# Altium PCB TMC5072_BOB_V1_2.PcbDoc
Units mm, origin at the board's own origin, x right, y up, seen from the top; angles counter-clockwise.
Board outline 25.4 x 35.56 mm, 4 copper layers (Top, GND, VM, Bottom), stack 0.704 mm thick; 32 components, 35 nets, 115 pads, 104 vias.
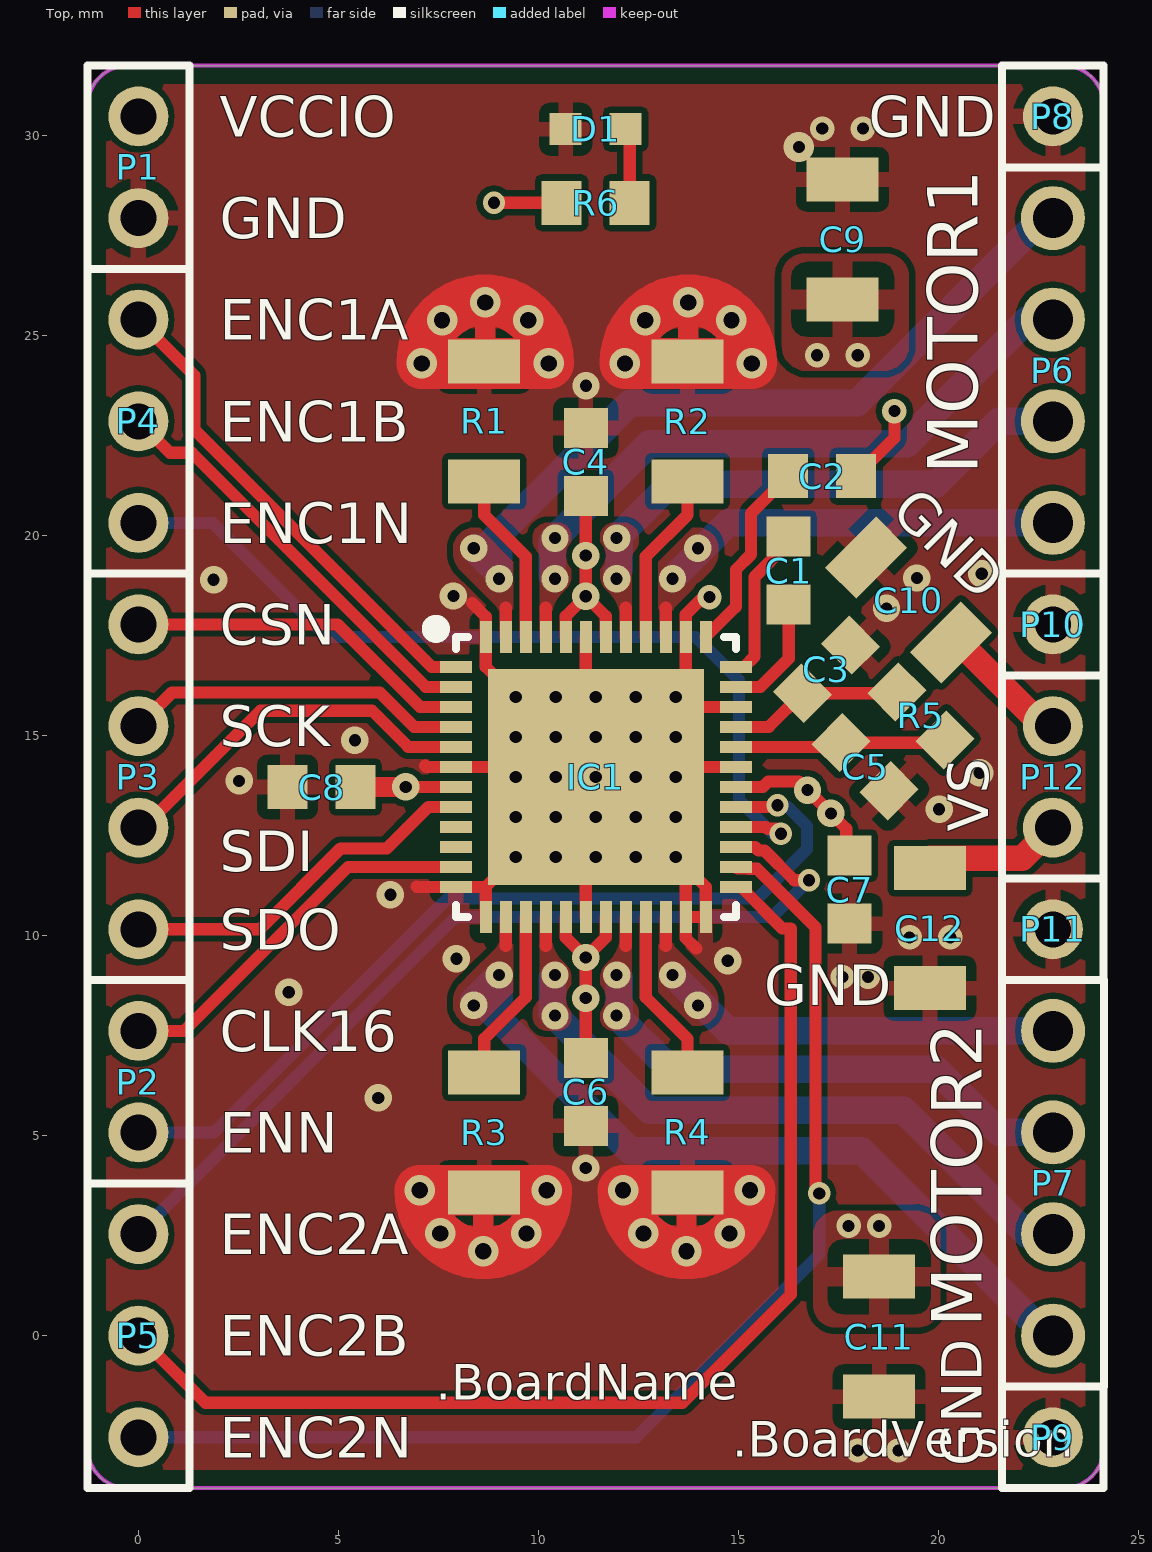
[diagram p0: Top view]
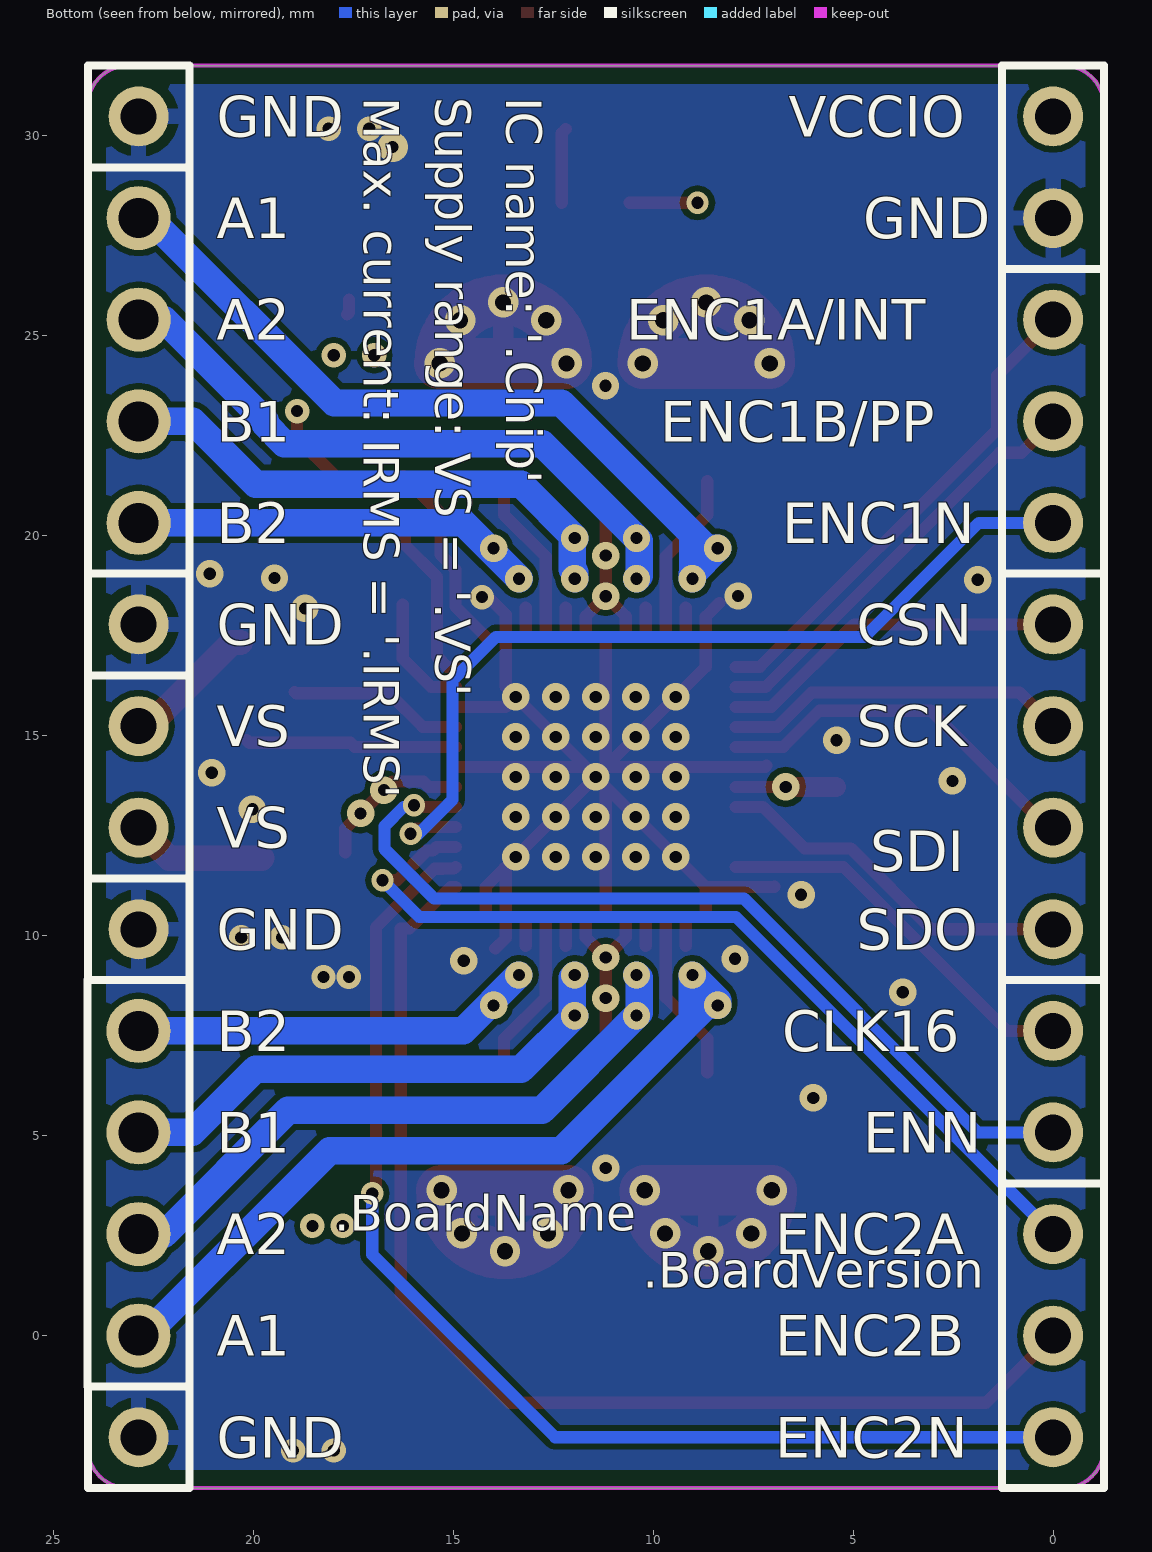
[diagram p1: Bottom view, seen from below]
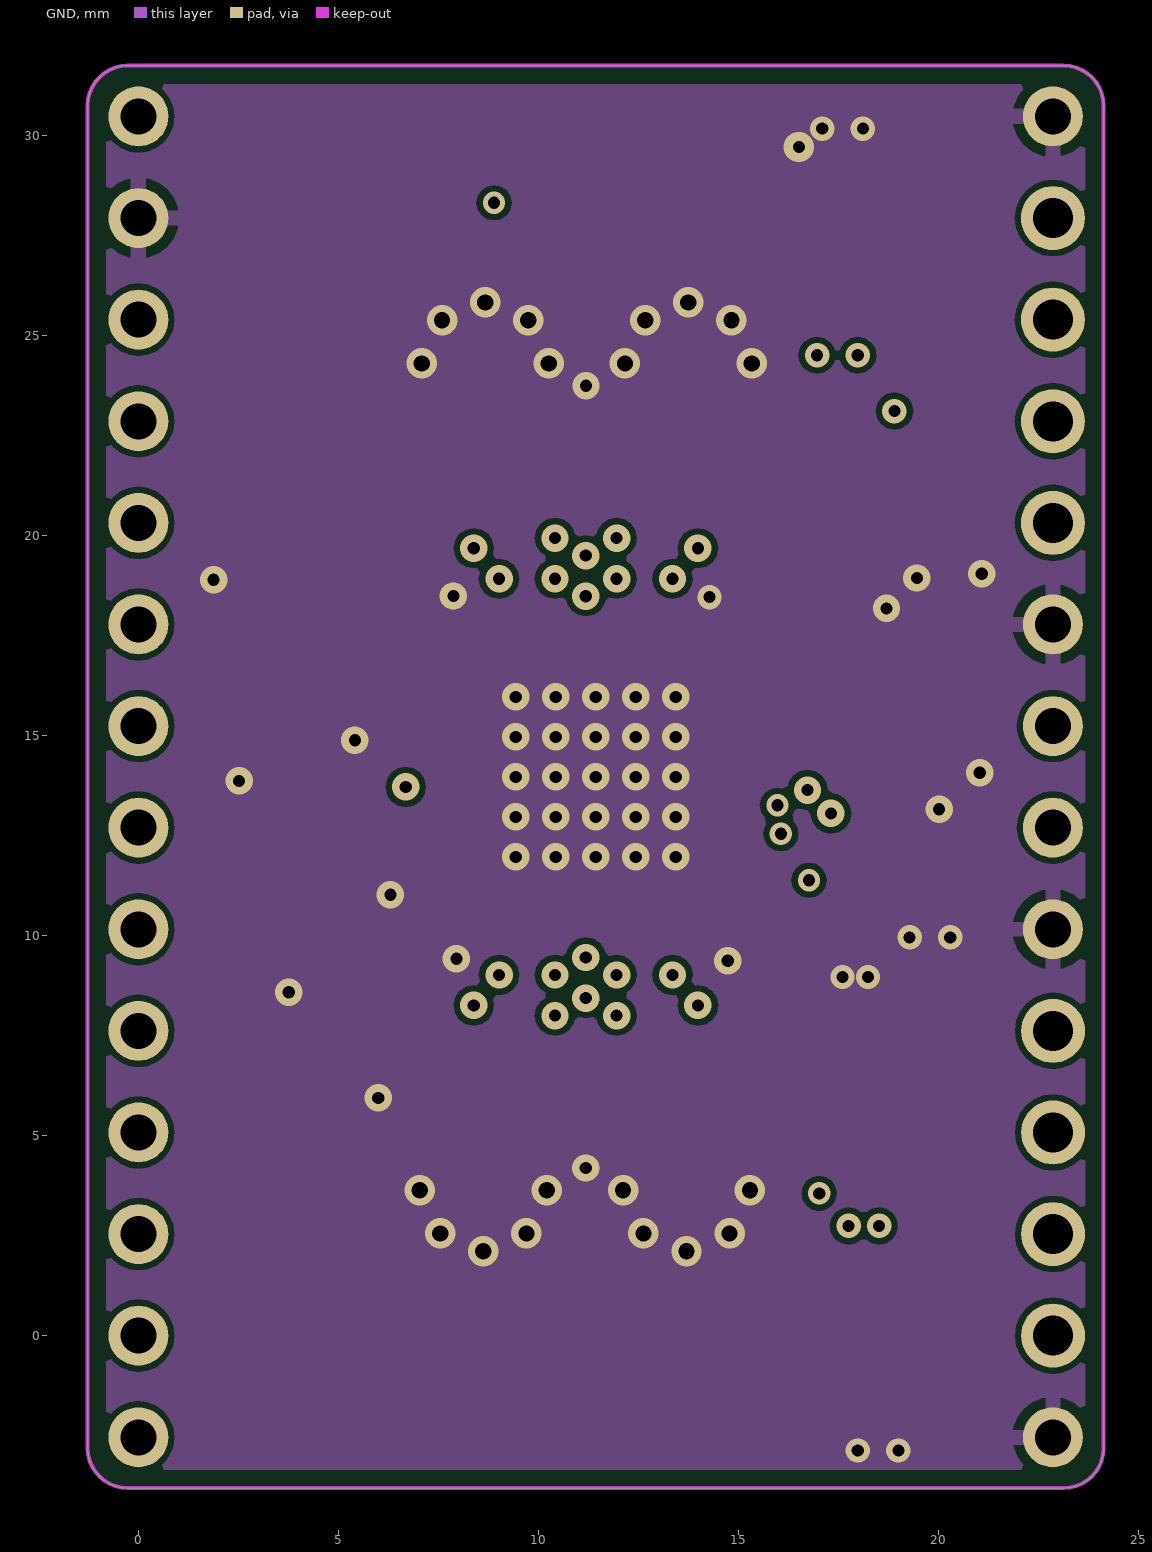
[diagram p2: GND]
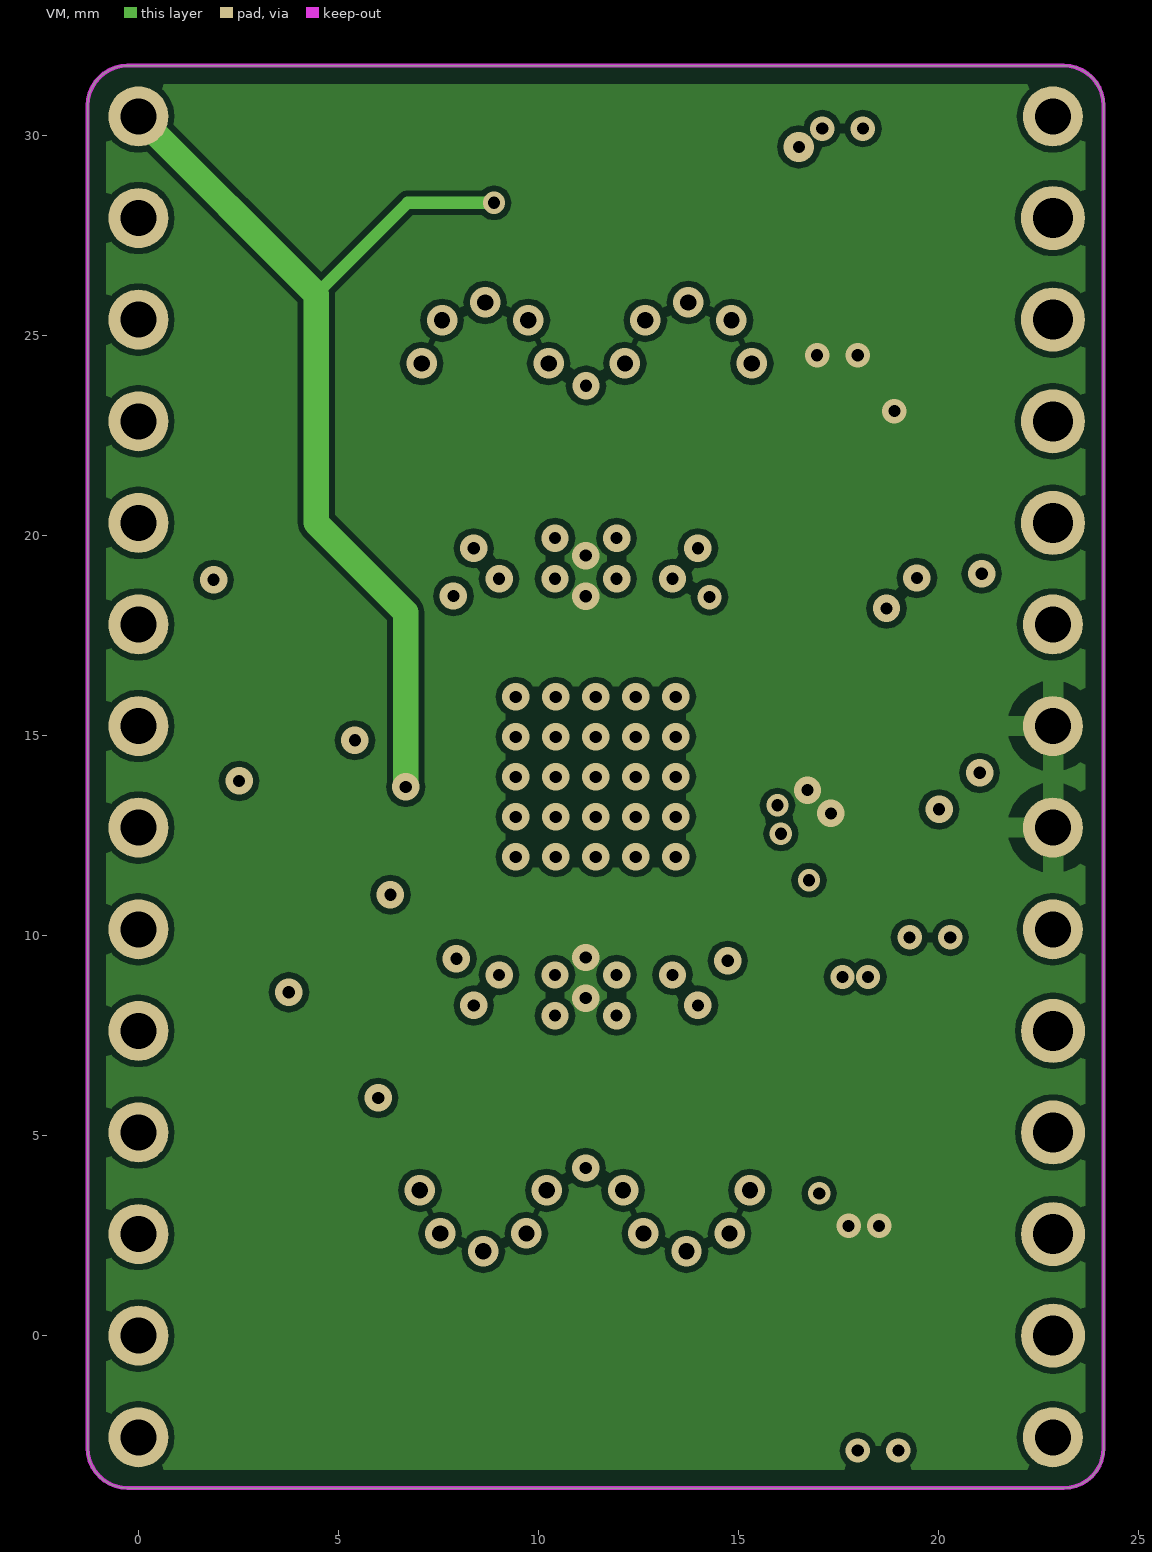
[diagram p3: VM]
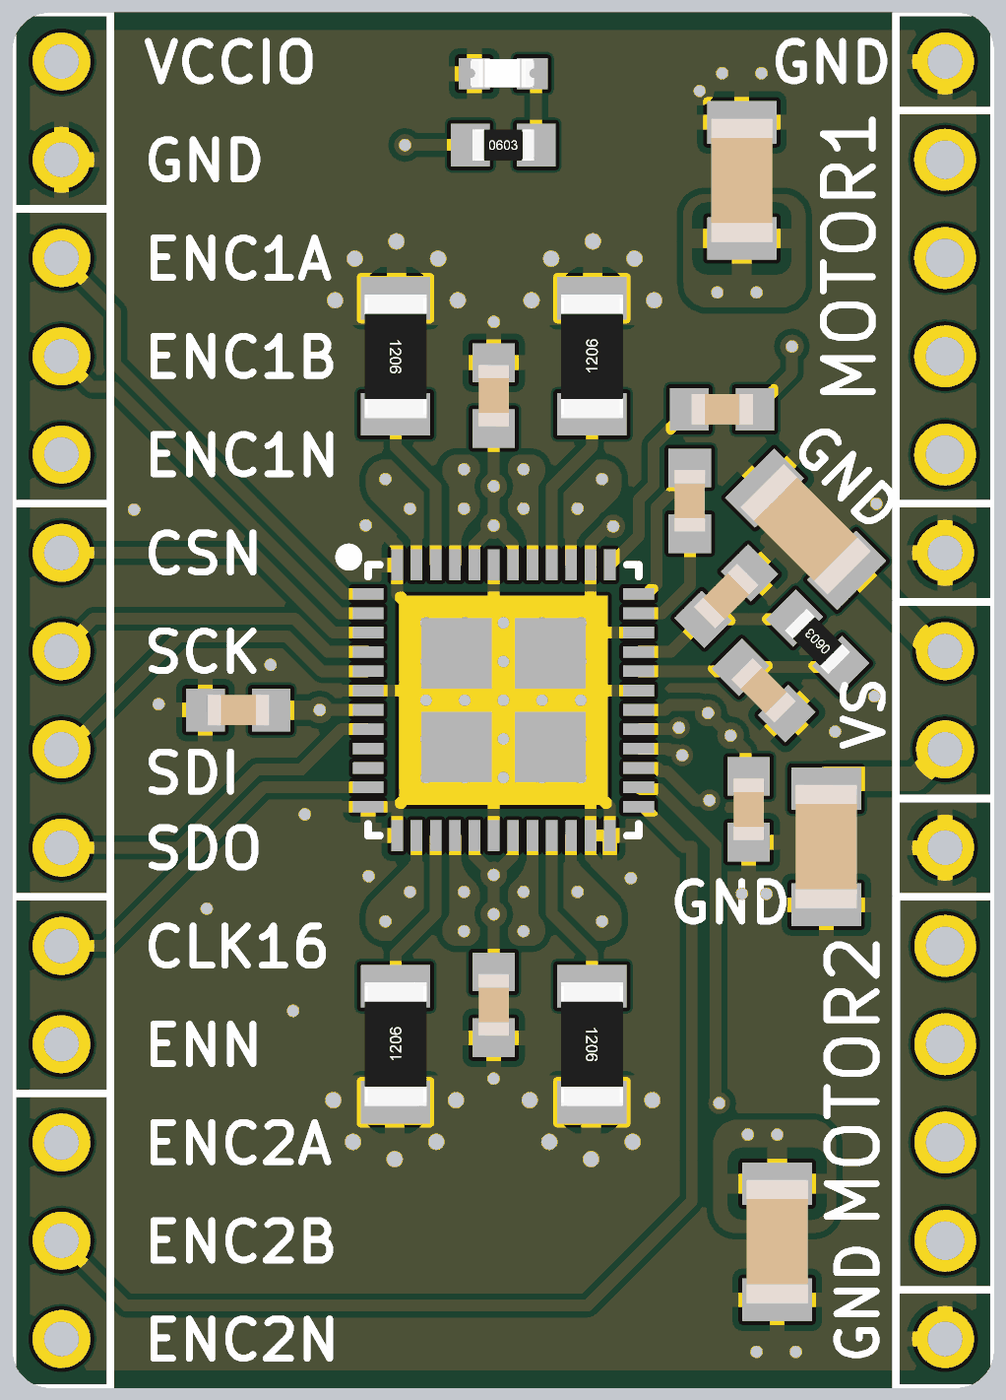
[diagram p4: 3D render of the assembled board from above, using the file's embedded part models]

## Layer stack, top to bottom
Top Solder: solder mask 0.0102, Solder Resist, Dk 3.5
Top: signal copper 0.035
Dielectric 1: core 0.2, FR-4, Dk 4.8
GND: signal copper 0.0175
Dielectric 2: prepreg 0.127, FR-4, Dk 4.2
VM: signal copper 0.0356
Dielectric4: core 0.254, FR-4, Dk 4.2
Bottom: signal copper 0.035
Bottom Solder: solder mask 0.0102, Solder Resist, Dk 3.5

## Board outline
-1.27,-2.81 ccw(c-0.27,-2.81) -0.27,-3.81 23.13,-3.81 ccw(c23.13,-2.81) 24.13,-2.81 24.13,30.75 ccw(c23.13,30.75) 23.13,31.75 -0.27,31.75 ccw(c-0.27,30.75) -1.27,30.75

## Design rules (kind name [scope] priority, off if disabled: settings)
Clearance BoardOutlineClearance [OnLayer('Keep-Out Layer')] p1: gap=0.4 ignorepadtopadclearanceinfootprint=FALSE except(0: Arc-Hole Track-Hole SMDPad-Hole THPad-Hole Via-Hole Fill-Hole Poly-Hole Region-Hole Text-Hole)
Clearance "Fiducial Clearance" [HasFootprint('FIDUCIAL_40MIL')] p2: gap=0.66 ignorepadtopadclearanceinfootprint=FALSE except(0: Arc-Hole Track-Hole SMDPad-Hole THPad-Hole Via-Hole Fill-Hole Poly-Hole Region-Hole Text-Hole)
Clearance "Mounting Hole Clearance" [(HoleDiameter >= 110) And  IsPad  And ((PadYSize_AllLayers - HoleDiameter)  <=  1)] p3: gap=0.762 ignorepadtopadclearanceinfootprint=FALSE except(0: Arc-Hole Track-Hole SMDPad-Hole THPad-Hole Via-Hole Fill-Hole Poly-Hole Region-Hole Text-Hole)
Clearance [All] p4: gap=0.152 ignorepadtopadclearanceinfootprint=FALSE except(0: Arc-Hole Track-Hole SMDPad-Hole THPad-Hole Via-Hole Fill-Hole Poly-Hole Region-Hole Text-Hole)
ComponentClearance [All] p1: gap=0 collisioncheckmode=3 verticalgap=0.254 showdistances=FALSE
DiffPairsRouting [All] p1 off: maxlimit=0.254 minlimit=0.191 mostfreqgap=0.254 toplayer_prefgap=0.191 toplayer_minwidth=0.191 toplayer_maxwidth=0.191 toplayer_prefwidth=0.191 midlayer1_prefgap=0.191 midlayer1_minwidth=0.191 midlayer1_maxwidth=0.191 midlayer1_prefwidth=0.191 midlayer2_mingap=0.254 midlayer2_minwidth=0.381 midlayer2_maxwidth=0.381 midlayer2_prefwidth=0.381 bottomlayer_prefgap=0.191 bottomlayer_minwidth=0.191 bottomlayer_maxwidth=0.191 bottomlayer_prefwidth=0.191 maxuncoupledlength=12.7
HoleSize [All] p1: absolutevalues=TRUE maxlimit=2540 minlimit=0.3 maxpercent=80.000 minpercent=20.000
HoleToHoleClearance [All] p1: gap=0.203 allowstackedmicrovias=TRUE
MatchedLengths "SD_CARD MatchedLengths" [InNetClass('SD_CARD')] p1: tolerance=0.254 checknetsindiffpair=FALSE checkdiffpairvsdiffpair=TRUE checkxsignals=TRUE checkothers=TRUE
MinimumAnnularRing MinimumViaAnnualRing [All] p1: minimumring=0.125
MinimumSolderMaskSliver STM32_MinimumSolderMaskSliver [(InComponent('STM1') AND InComponent('STM2')) vs (InComponent('STM1') AND InComponent('STM2'))] p1: minsoldermaskwidth=0.025
MinimumSolderMaskSliver USB_HUB_MinimumSolderMaskSliver [InComponent('USB_HUB')] p2: minsoldermaskwidth=0.025
MinimumSolderMaskSliver [All] p3 off: minsoldermaskwidth=0.038
PasteMaskExpansion TestPadPasteMaskExpansion [HasFootprint('SMD_TP_2X2_ROUND')] p1: expansion=-2
PasteMaskExpansion [All] p2: expansion=0
PlaneClearance [All] p1: clearance=1.016
PlaneConnect VM_PlaneConnect [OnLayer('VM') AND InNet('VM')] p1: planeconnectstyle=Relief reliefexpansion=0.508 reliefentries=4 reliefconductorwidth=0.508 reliefairgap=0.254
PlaneConnect [All] p2: planeconnectstyle=Relief reliefexpansion=0.508 reliefentries=4 reliefconductorwidth=0.254 reliefairgap=0.254
PolygonConnect VSAViaConnectStyle [InNet('VM') AND IsVia] p1: connectstyle=Direct reliefconductorwidth=0.508 reliefentries=4 polygonreliefangle="90 Angle" airgapwidth=0.203
PolygonConnect VSAConnectStyle [InNet('VM')] p2: connectstyle=Relief reliefconductorwidth=0.508 reliefentries=4 polygonreliefangle="90 Angle" airgapwidth=0.381
PolygonConnect MotorPhaceConnectStyle [(IsVia OR IsPad) AND InNetClass('MotorPower')] p3: connectstyle=Direct reliefconductorwidth=0.254 reliefentries=4 polygonreliefangle="90 Angle" airgapwidth=0.254
PolygonConnect ThermalVias [IsVia] p4: connectstyle=Direct reliefconductorwidth=0.254 reliefentries=4 polygonreliefangle="90 Angle" airgapwidth=0.254
PolygonConnect [All] p5: connectstyle=Relief reliefconductorwidth=0.381 reliefentries=4 polygonreliefangle="90 Angle" airgapwidth=0.254
RoutingVias [All] p1: holewidth=0.305 width=0.559 viastyle="Through Hole" minholewidth=0.305 minwidth=0.559 maxholewidth=0.305 maxwidth=1.27
ShortCircuit [All] p1 off: allowed=FALSE
SilkToBoardRegionClearance [All] p1 off:
SilkToSilkClearance [All] p1 off: silktosilkclearance=0.254
SilkToSolderMaskClearance [IsPad] p1 off: minsilkscreentomaskgap=0.254 clearancetoexposedcopper=TRUE
SolderMaskExpansion FiducialSolderMaskExpansion [HasFootprint('FIDUCIAL_40MIL')] p1: expansion=0.66
SolderMaskExpansion [All] p2: expansion=0.102
UnRoutedNet [All] p1 off:
Width VIN_Width [InNetClass('PWR_VIN')] p1: maxlimit=7.62 minlimit=5.08 preferedwidth=5.334
Width Other_Width [All] p2: maxlimit=2540 minlimit=0.203 preferedwidth=0.3 minimp=50.000000 maximp=50.000000 favimp=50.000000
17 further rules are at their usual default settings.

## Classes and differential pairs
differential pair class USB_DIFF: STM_USB STM_USB_D

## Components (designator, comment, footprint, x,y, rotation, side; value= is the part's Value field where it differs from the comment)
C1 "22nF" C0603 16.256,19.126 r90 top
C2 "100nF" C0603 17.094,21.488 r180 top
C3 "470nF" C0603 17.2,16.662 r45 top
C4 "100nF" C0603 11.184,21.844 r90 top
C5 "4.7uF" C0603 18.165,14.224 r315 top
C6 "100nF" C0603 11.184,6.096 r90 top
C7 "100nF" C0603 17.78,11.151 r90 top
C8 "100nF" C0603 4.576,13.716 r180 top
C9 "10uF" C1206 17.602,27.407 r90 top
C10 "10uF" C1206 19.253,18.39 r135 top
C11 "10uF" C1206 18.517,-0.025 r270 top
C12 "10uF" C1206 19.787,10.185 r270 top
D1 "LED, Blue, SMD, 20mA, 2.8V, 465 nm" LED_0603 11.43,30.163 r180 top
IC1 "TMC5072-LA" TMC5072_QFN48_0.5_7.0X7.0 11.434,13.97 r270 top
P1 "VCC" 2_PIN_THT 0,30.48 r180 top
P2 "VCC" 2_PIN_THT 0,7.62 r180 top
P3 "SPI" 4_PIN_THT 0,10.16 r0 top
P4 "ENC1" 3_PIN_THT 0,20.32 r0 top
P5 "ENC2" 3_PIN_THT 0,-2.54 r0 top
P6 "MOTOR1" 4_PIN_THT_1mm_hole 22.86,27.94 r180 top
P7 "MOTOR2" 4_PIN_THT_1mm_hole 22.864,0 r0 top
P8 "GND" TH_PIN 22.86,30.48 r0 top
P9 "GND" TH_PIN 22.86,-2.54 r90 top
P10 "GND" TH_PIN 22.86,17.78 r0 top
P11 "GND" TH_PIN 22.86,10.16 r0 top
P12 "PWR" 2_PIN_THT 22.86,12.7 r0 top
R1 "0R27/1%/R1206" R1206 8.644,22.86 r270 top
R2 "0R27/1%/R1206" R1206 13.724,22.86 r90 top
R3 "0R27/1%/R1206" R1206 8.644,5.08 r90 top
R4 "0R27/1%/R1206" R1206 13.724,5.08 r270 top
R5 "2R2/1%/" R0603 19.562,15.494 r135 top
R6 "1k" R0603 11.43,28.321 r0 top

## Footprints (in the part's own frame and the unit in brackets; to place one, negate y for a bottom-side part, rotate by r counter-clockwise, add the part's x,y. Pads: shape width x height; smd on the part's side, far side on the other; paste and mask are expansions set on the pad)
2_PIN_THT [mm]
  round 1.5 hole 0.9: 1(0,0) 2(0,2.54)
  silkscreen extent -1.27,-1.27 1.27,3.81
3_PIN_THT [mm]
  round 1.5 hole 0.9: 1(0,0) 2(0,2.54) 3(0,5.08)
  silkscreen extent -1.27,-1.27 1.27,6.35
4_PIN_THT [mm]
  round 1.5 hole 0.9: 1(0,0) 2(0,2.54) 3(0,5.08) 4(0,7.62)
  silkscreen extent -1.27,-1.27 1.27,8.89
4_PIN_THT_1mm_hole [mm]
  round 1.6 hole 1: 1(0,0) 2(0,2.54) 3(0,5.08) 4(0,7.62)
  silkscreen extent -1.27,-1.27 1.27,8.89
C0603 [mm] "0603 ceramic capacitor"
  rect 1x1.1 smd: 1(-0.85,0) 2(0.85,0)
  body extent -0.8,-0.4 0.8,0.4, height 0.8
C1206 [mm] "1206 ceramic capacitor"
  rect 1.1x1.8 smd: 1(-1.5,0) 2(1.5,0)
  body extent -1.6,-0.8 1.6,0.8, height 0.76
LED_0603 [mm]
  rect 0.8x0.8 smd: 1(-0.75,0) 2(0.75,0)
  body extent -0.8,-0.38 0.85,0.35, height 0.68
R0603 [mm] "0603 resistor"
  rect 1x1.1 smd: 1(-0.85,0) 2(0.85,0)
  body extent -0.8,-0.4 0.8,0.4, height 0.45
R1206 [mm] "1206 resistor"
  rect 1.1x1.8 smd: 1(-1.5,0) 2(1.5,0)
  body extent -1.6,-0.8 1.6,0.8, height 0.6
TH_PIN [mm]
  round 1.5 hole 0.9: 1(0,0)
  silkscreen extent -1.27,-1.27 1.27,1.27
TMC5072_QFN48_0.5_7.0X7.0 [mm]
  rect 0.3x0.8 smd: 1(-2.75,-3.5) 2(-2.25,-3.5) 3(-1.75,-3.5) 4(-1.25,-3.5) 5(-0.75,-3.5) 6(-0.25,-3.5) 7(0.25,-3.5) 8(0.75,-3.5) 9(1.25,-3.5) 10(1.75,-3.5) 11(2.25,-3.5) 12(2.75,-3.5) 25(2.75,3.5) 26(2.25,3.5) 27(1.75,3.5) 28(1.25,3.5) 29(0.75,3.5) 30(0.25,3.5) 31(-0.25,3.5) 32(-0.75,3.5) 33(-1.25,3.5) 34(-1.75,3.5) 35(-2.25,3.5) 36(-2.75,3.5)
  rect 0.8x0.3 smd: 13(3.5,-2.75) 14(3.5,-2.25) 15(3.5,-1.75) 16(3.5,-1.25) 17(3.5,-0.75) 18(3.5,-0.25) 19(3.5,0.25) 20(3.5,0.75) 21(3.5,1.25) 22(3.5,1.75) 23(3.5,2.25) 24(3.5,2.75) 37(-3.5,2.75) 38(-3.5,2.25) 39(-3.5,1.75) 40(-3.5,1.25) 41(-3.5,0.75) 42(-3.5,0.25) 43(-3.5,-0.25) 44(-3.5,-0.75) 45(-3.5,-1.25) 46(-3.5,-1.75) 47(-3.5,-2.25) 48(-3.5,-2.75)
  rect 5.4x5.4 smd paste-25.4: 49(0,0)
  silkscreen extent -3.8,-4.1 3.5,3.5, body extent -3.5,-3.5 3.5,3.5, height 0.9

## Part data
C1: library part Capacitor, "Ceramic capacitor", MPN=MC0603B223K500CT, Voltage rating=50V
C2 C4 C6 C7: library part Capacitor, "Ceramic capacitor", MPN=MC0603F104M500CT, Voltage rating=50V
C3: library part Capacitor, "Ceramic capacitor", MPN=MC0603X474K160CT, Voltage rating=16V
C5: library part Capacitor, "Ceramic capacitor", MPN=MC0603X475K100CT, Voltage rating=10V
C8: library part Capacitor, "Ceramic capacitor", Manufacturer=Multicomp, MPN=MC0603F104M500CT, Voltage rating=50V
C9 C10 C11 C12: library part "10 µF, 25 V, ± 10%, X5R, MC Series, 1206 [3216 Metric]", "SMD Multilayer Ceramic Capacitor, 1206 [3216 Metric], 10 µF, 25 V, ± 10%, X5R, MC Series", MPN=MC1206X106K250CT, Voltage rating=25V
D1: Colour=Blue, Current rating=20mA, MPN=LTST-C191TBKT-5A
IC1: "Dual low-noise operation controllerfor up to two 2-phase bipolar stepper motors, with SPI, Step/Dir, UART, QFN48(7x7)"
P1 P2 P12: library part "Header 2", "Header, 2-Pin"
P3: library part "Header 4", "Header, 4-Pin"
P4 P5: library part "Header 3", "Header, 3-Pin"
P6 P7: library part "Wire-To-Board Connector, 2.5 mm, 4 Contacts, Header, EH Series, Through Hole, 1 Rows", "Wire-To-Board Connector, 2.5 mm, 4 Contacts, Header, EH Series, Through Hole, 1 Rows", MPN=B4B-EH-A
P8 P9 P10 P11: library part PIN
R1 R2 R3 R4: library part Resistor, "Resistor", MPN=RCWE1206R270FKEA, Power rating=0.5W, Resistance=0R27, Temp coefficient=*ppm, Voltage rating=*V
R5: library part Resistor, "Resistor", MPN=MC0063W060312R2, Power rating=*mW, Resistance=2R2, Temp coefficient=*ppm, Voltage rating=*V
R6: library part "1 kohm, 50 V, 0603 [1608 Metric], 63 mW, ± 1%, MC Series", "1 kohm, 50 V, 0603 [1608 Metric], 63 mW, ± 1%, MC Series", MPN=MC0063W060311K, PowerRating=63mW, Temp coefficient=*ppm, VoltageRating=50V

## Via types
v1: diameter 0.686, hole 0.305, Top to Bottom, tented both sides, 58 vias
v2: diameter 0.762, hole 0.406, Top to Bottom, tented both sides, 20 vias
v3: diameter 0.61, hole 0.305, Top to Bottom, tented both sides, 14 vias
v4: diameter 0.688, hole 0.305, Top to Bottom, tented both sides, 6 vias
v5: diameter 0.559, hole 0.305, Top to Bottom, tented both sides, 5 vias
v6: diameter 0.757, hole 0.3, Top to Bottom, tented both sides, 1 vias

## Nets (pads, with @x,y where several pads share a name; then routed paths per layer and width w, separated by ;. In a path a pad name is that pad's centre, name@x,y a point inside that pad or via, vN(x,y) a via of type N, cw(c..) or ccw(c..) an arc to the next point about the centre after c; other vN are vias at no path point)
5V_OUT: C5.1 IC1.32 R5.1 | length 5.3
  Top w0.305: IC1.32 17.459,14.72 C5.1 20.095,14.825 R5.1
BR1A: IC1.46 R1.2 | length 4.3
  Top w0.305: R1.2 8.644,20.518 9.684,19.478 IC1.46
BR1B: IC1.40 R2.1 | length 4.3
  Top w0.305: IC1.40 12.684,19.478 13.724,20.518 R2.1
BR2A: IC1.15 R3.2 | length 4.3
  Top w0.305: R3.2 8.644,7.422 9.684,8.462 IC1.15
BR2B: IC1.21 R4.1 | length 4.3
  Top w0.305: IC1.21 12.684,8.462 13.724,7.422 R4.1
CLK16: IC1.11 P2.1 | length 9.6
  Top w0.305: P2.1 1.143,7.62 5.243,11.72 IC1.11
CPI: C1.2 IC1.36 | length 4
  Top w0.305: IC1.36 15.145,16.72 15.401,16.976 15.401,18.97 16.206,19.774 16.206,19.976 C1.2
CPO: C1.1 IC1.35 | length 3
  Top w0.305: IC1.35 15.549,16.22 16.256,16.927 C1.1
CSN: IC1.3 P3.4 | length 8.8
  Top w0.305: P3.4 4.976,17.78 7.036,15.72 IC1.3
ENC1N: IC1.28 P4.1 | length 22.2
  Top w0.305: IC1.28 15.689,12.72 15.735,12.675 15.934,12.675 v5(16.061,12.548)
  Bottom w0.305: P4.1 1.854,20.32 4.704,17.47 13.924,17.47 15.011,16.383 15.011,13.398 15.862,12.548 v5(16.061,12.548)
ENC2A: IC1.27 P5.3 | length 22.6
  Top w0.305: IC1.27 15.415,12.22 15.503,12.132 15.65,12.132 16.397,11.385 v5(16.764,11.385)
  Bottom w0.305: P5.3 7.93,10.47 15.849,10.47 v5(16.764,11.385)
ENC2B: IC1.25 P5.2 | length 36.8
  Top w0.305: P5.2 1.676,-1.676 13.603,-1.676 16.307,1.028 16.307,10.182 ; IC1.25 15.056,11.22 16.094,10.182 16.307,10.182 ; 16.307,2.475 16.307,10.182
ENC2N: IC1.26 P5.1 | length 29.7
  Top w0.305: IC1.26 14.977,11.677 15.246,11.677 15.248,11.675 15.461,11.675 16.925,10.21 16.925,3.649 v5(17.018,3.556)
  Bottom w0.305: P5.1 12.446,-2.54 17.018,2.032 v5(17.018,3.556)
ENN: IC1.29 P2.2 | length 22.2
  Top w0.305: IC1.29 v5@16.002,13.22
  Bottom w0.305: P2.2 1.88,5.08 7.727,10.927 15.474,10.927 16.713,12.167 16.713,12.737 16.23,13.22 v5@16.002,13.22
  other v5: 15.977,13.259
GND: C3.2 C4.2 C5.2 C6.1 C7.1 C8.2 C9.2 C10.2 C11.2 C12.2 D1.2 IC1.6 IC1.12 IC1.13 IC1.18 IC1.23 IC1.24 IC1.31 IC1.34 IC1.38 IC1.43 IC1.48 IC1.49 P1.2 P8.1 P9.1 P10.1 P11.1 R1.1 R2.2 R3.1 R4.2 | length 78.6
  Top w0.305: 6.96,11.227 6.966,11.22 IC1.12 8.684,11.22 ; 7.163,14.249 7.192,14.22 IC1.6 IC1.49@11.184,14.22 ; 8.344,18.313 8.684,17.973 IC1.48 8.684,16.72 v1(9.434,15.97) v1(10.434,14.97) IC1.49@11.184,14.22 ; IC1.13 8.684,11.22 ; IC1.18 IC1.49@11.184,13.72 ; IC1.43 IC1.49@11.184,14.22 ; 13.945,9.677 13.684,9.938 IC1.23 ; v3(14.275,18.464) 14.121,18.464 13.684,18.028 IC1.38 13.684,16.22 v1(13.434,15.97) ; IC1.31 IC1.49@11.684,14.22 ; IC1.34 13.684,15.72 v1(13.434,15.97) ; 8.684,11.22 v1(9.434,11.97) v1(10.434,12.97) IC1.49@11.184,13.72 ; IC1.49@11.184,13.72 v1(11.434,13.97) ; IC1.49@11.184,14.22 v1(11.434,13.97) ; v1(11.434,13.97) v1(12.434,12.97) v1(13.434,11.97) IC1.49@13.718,11.686 ; v1(11.434,13.97) IC1.49@11.684,14.22 ; IC1.49@11.684,14.22 v1(12.434,14.97) v1(13.434,15.97) ; IC1.23 13.684,11.652 IC1.49@13.718,11.686 ; IC1.23 IC1.24 14.184,11.22 IC1.49@13.718,11.686
  Top w0.508: v2@8.621,2.248 R3.1@8.621,3.634 ; R1.1@8.668,24.306 v2@8.668,25.692 ; v2@13.701,2.248 R4.2@13.701,3.634 ; R2.2@13.748,24.306 v2@13.748,25.692
  Top w1.27: v2(7.034,3.634) ccw(c8.621,3.634) v2(10.208,3.634) 8.621,3.634 v2(7.034,3.634) ; v2(7.081,24.306) cw(c8.668,24.306) v2(10.255,24.306) 8.668,24.306 v2(7.081,24.306) ; v2(12.114,3.634) ccw(c13.701,3.634) v2(15.288,3.634) 13.701,3.634 v2(12.114,3.634) ; v2(12.161,24.306) cw(c13.748,24.306) v2(15.335,24.306) 13.748,24.306 v2(12.161,24.306)
  other v1: 11.18,4.191 14.732,9.373 7.95,9.423 6.299,11.024 10.434,11.97 11.434,11.97 12.434,11.97 9.434,12.97 11.434,12.97 13.434,12.97 2.515,13.868 9.434,13.97 10.434,13.97 12.434,13.97 13.434,13.97 5.41,14.884 9.434,14.97 11.434,14.97 13.434,14.97 10.434,15.97 11.434,15.97 12.434,15.97 18.701,18.18 7.874,18.491 19.463,18.942 11.189,23.749
  other v2: 8.621,2.11 13.701,2.11 7.543,2.556 9.699,2.556 12.623,2.556 14.779,2.556 7.59,25.384 9.745,25.384 12.67,25.384 14.825,25.384 8.668,25.83 13.748,25.83
  other v3: 17.983,-2.872 18.999,-2.872 17.602,8.968 18.237,8.968 19.279,9.955 20.295,9.955 17.094,30.177 18.11,30.177
  other v4: 5.994,5.944 3.759,8.585 20.015,13.159 21.031,14.072 1.88,18.898 21.082,19.05
  other v6: 16.51,29.718
INT/ENC1A: IC1.1 P4.3 | length 12.3
  Top w0.305: P4.3 1.397,24.003 1.397,22.652 7.329,16.72 IC1.1
NetD1_1: D1.1 R6.2 | length 1.9
  Top w0.305: D1.1 12.28,30.063 R6.2
O1A1: IC1.47 P6.1 | length 20.8
  Top w0.305: IC1.47 9.184,18.2
  Bottom w0.686: v1@9.013,18.923 v1@9.013,19.054 ; v1(9.017,18.923) 9.017,19.05 v1@9.013,19.054 ; P6.1 22.592,27.94 17.969,23.317 12.289,23.317 9.013,20.041 ; v1@9.013,19.054 v1(8.382,19.685) 8.657,19.685 9.013,20.041 ; v1@9.013,19.054 9.013,20.041
O1A2: IC1.45 P6.2 | length 16.6
  Top w0.305: IC1.45 10.184,18.2
  Bottom w0.686: v1@10.41,18.923 10.342,18.991 10.342,19.871 12.772,22.301 19.216,22.301 19.698,22.783 19.698,22.877 22.221,25.4 P6.2
  other v1: 10.414,18.923 10.414,19.939
O1B1: IC1.41 P6.3 | length 13.9
  Top w0.305: IC1.41 12.184,18.2
  Bottom w0.686: v1@11.95,18.923 11.95,19.083 12.023,19.155 12.023,19.849 11.95,19.921 11.95,19.939 13.297,21.285 19.935,21.285 21.509,22.86 P6.3
  other v1: 11.955,18.923 11.955,19.939
O1B2: IC1.39 P6.4 | length 10.8
  Top w0.305: IC1.39 13.184,18.2
  Bottom w0.686: v1@13.347,18.923 14.744,20.32 P6.4
  other v1: 13.352,18.923 13.987,19.685
O2A1: IC1.14 P7.1 | length 20.8
  Top w0.305: 9.184,9.74 IC1.14
  Bottom w0.686: P7.1 22.708,0 18.085,4.623 12.294,4.623 9.017,7.899 ; 9.017,7.899 8.661,8.255 v1(8.382,8.255) 8.382,8.382 v1(9.017,9.017) 9.017,7.899
O2A2: IC1.16 P7.2 | length 16.5
  Top w0.305: 10.184,9.74 IC1.16
  Bottom w0.686: v1(10.414,9.017) 10.346,8.949 10.346,8.069 v1(10.414,8.001) 12.776,5.639 19.126,5.639 22.225,2.54 P7.2
O2B1: IC1.20 P7.3 | length 13.9
  Top w0.305: 12.184,9.74 IC1.20
  Bottom w0.686: v1(11.955,9.017) 12.023,8.949 12.023,8.069 v1(11.955,8.001) 13.301,6.655 19.939,6.655 21.514,5.08 P7.3
O2B2: IC1.22 P7.4 | length 10.8
  Top w0.305: 13.184,9.74 IC1.22
  Bottom w0.686: v1(13.352,9.017) 14.749,7.62 P7.4
  other v1: 13.987,8.255
PP/ENC1B: IC1.2 P4.2 | length 10.7
  Top w0.305: P4.2 0.787,22.073 1.33,22.073 7.183,16.22 IC1.2
SCK: IC1.4 P3.3 | length 8.6
  Top w0.305: P3.3 0.838,16.078 6.031,16.078 6.89,15.22 IC1.4
SDI: IC1.5 P3.2 | length 9.5
  Top w0.305: P3.2 0.127,12.7 3.048,15.621 5.842,15.621 6.743,14.72 IC1.5
SDO: IC1.8 P3.1 | length 9.2
  Top w0.305: P3.1 3.036,10.16 5.054,12.177 6.208,12.177 7.251,13.22 IC1.8
SWION: IC1.10
SWIOP: IC1.9
VCC: C3.1 IC1.33 R5.2 | length 4.4
  Top w0.305: IC1.33 15.758,15.22 C3.1 18.928,16.061 R5.2
VCC_IO: C8.1 IC1.7 P1.1 R6.1 | length 29.1
  Top w0.305: v1@6.682,13.716 6.686,13.72 IC1.7 ; v5(8.89,28.321) R6.1
  Top w0.508: C8.1 v1@6.682,13.716
  VM w0.305: 4.445,26.035 6.731,28.321 v5(8.89,28.321)
  VM w0.635: P1.1 4.445,26.035 4.445,20.32 6.682,18.083 v1(6.682,13.72)
VCP: C2.2 IC1.37 | length 4.9
  Top w0.305: IC1.37 14.935,18.221 14.935,19.15 15.316,19.531 15.316,20.56 C2.2
VM: C2.1 C4.1 C6.2 C7.2 C9.1 C10.1 C11.1 C12.1 IC1.17 IC1.19 IC1.30 IC1.42 IC1.44 P12.1 P12.2 | length 22.5
  Top w0.305: IC1.17 10.684,9.954 v1(11.184,9.454) ; IC1.44 10.684,17.986 v1(11.184,18.486) ; C6.2@11.184,7.2 v1(11.184,9.454) ; C4.1@11.184,20.74 v1(11.184,18.486) ; IC1.19 11.684,9.954 v1(11.184,9.454) ; IC1.42 11.684,17.986 v1(11.184,18.486) ; IC1.30 15.612,13.72 15.747,13.855 16.511,13.855 17.695,12.671 C7.2@17.695,12.087 ; C9.1 17.602,25.578 C9.1@17.653,25.527 ; C2.1 18.898,22.442 v3(18.898,23.114)
  Top w0.635: C12.1@19.787,11.939 22.099,11.939 P12.1 ; C10.1 20.525,17.329 22.614,15.24 P12.2
  other v1: 11.184,8.438 17.311,13.056 16.727,13.64 11.184,19.502
  other v3: 17.755,2.745 18.517,2.745 16.967,24.51 17.983,24.51

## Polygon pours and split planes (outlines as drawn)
GND on GND "TOP_GND" (solid, pour order 43): -1.27,-2.81 ccw(c-0.27,-2.81) -0.27,-3.81 23.13,-3.81 ccw(c23.13,-2.81) 24.13,-2.81 24.13,30.75 ccw(c23.13,30.75) 23.13,31.75 -0.27,31.75 ccw(c-0.27,30.75) -1.27,30.75
GND on Bottom "TOP_GND" (solid, pour order 42): -1.27,-2.81 ccw(c-0.27,-2.81) -0.27,-3.81 23.13,-3.81 ccw(c23.13,-2.81) 24.13,-2.81 24.13,30.75 ccw(c23.13,30.75) 23.13,31.75 -0.27,31.75 ccw(c-0.27,30.75) -1.27,30.75
VM on VM "VM_VM" (solid, pour order 41): -1.27,-2.81 ccw(c-0.27,-2.81) -0.27,-3.81 23.13,-3.81 ccw(c23.13,-2.81) 24.13,-2.81 24.13,30.75 ccw(c23.13,30.75) 23.13,31.75 -0.27,31.75 ccw(c-0.27,30.75) -1.27,30.75
O1A2 on Top "TOP_O2A2" (solid, pour order 40): 10.033,17.78 10.033,19.304 10.033,19.461 ccw(c9.86,19.461) 9.982,19.583 cw(c10.289,19.89) 9.855,19.89 9.855,19.939 cw(c10.236,19.939) 10.236,20.32 10.262,20.32 10.49,20.32 cw(c10.49,19.99) 10.82,19.99 10.82,19.126 10.82,18.976 cw(c10.387,18.976) 10.693,18.669 10.571,18.547 ccw(c11.135,17.983) 10.338,17.983
O1B1 on Top "TOP_O2B1" (solid, pour order 39): 12.336,17.78 12.336,19.304 12.336,19.461 cw(c12.509,19.461) 12.386,19.583 ccw(c12.08,19.89) 12.513,19.89 12.513,19.939 ccw(c12.132,19.939) 12.132,20.32 12.107,20.32 11.878,20.32 ccw(c11.878,19.99) 11.548,19.99 11.548,19.126 11.548,18.976 ccw(c11.982,18.976) 11.675,18.669 11.797,18.547 cw(c11.234,17.983) 12.031,17.983
O2B1 on Top "TOP_O2B1" (solid, pour order 38): 12.336,10.16 12.336,8.636 12.336,8.479 ccw(c12.509,8.479) 12.386,8.357 cw(c12.08,8.05) 12.513,8.05 12.513,8.001 cw(c12.132,8.001) 12.132,7.62 12.107,7.62 11.878,7.62 cw(c11.878,7.95) 11.548,7.95 11.548,8.814 11.548,8.964 cw(c11.982,8.964) 11.675,9.271 11.797,9.393 ccw(c11.234,9.957) 12.031,9.957
O2A2 on Top "TOP_O2A2" (solid, pour order 37): 10.033,10.16 10.033,8.636 10.033,8.479 cw(c9.86,8.479) 9.982,8.357 ccw(c10.289,8.05) 9.855,8.05 9.855,8.001 ccw(c10.236,8.001) 10.236,7.62 10.262,7.62 10.49,7.62 ccw(c10.49,7.95) 10.82,7.95 10.82,8.814 10.82,8.964 ccw(c10.387,8.964) 10.693,9.271 10.571,9.393 cw(c11.135,9.957) 10.338,9.957
O1B2 on Top "TOP_O2A1" (solid, pour order 36): 12.971,17.653 cw(c13.662,18.344) 12.684,18.344 12.684,19.478 13.352,20.145 cw(c13.399,20.145) 13.399,20.193 13.987,20.193 cw(c13.987,19.685) 14.495,19.685 14.495,19.558 cw(c13.881,19.558) 14.315,19.124 13.987,18.796 13.441,18.251 ccw(c13.658,18.034) 13.352,18.034
O1A1 on Top "TOP_O2A1" (solid, pour order 35): 9.398,17.653 ccw(c8.707,18.344) 9.684,18.344 9.684,19.478 9.017,20.145 ccw(c8.969,20.145) 8.969,20.193 8.382,20.193 ccw(c8.382,19.685) 7.874,19.685 7.874,19.558 ccw(c8.487,19.558) 8.054,19.124 8.382,18.796 8.927,18.251 cw(c8.71,18.034) 9.017,18.034
O2B2 on Top "TOP_O2B2" (solid, pour order 34): 12.971,10.287 ccw(c13.662,9.596) 12.684,9.596 12.684,8.462 13.352,7.795 ccw(c13.399,7.795) 13.399,7.747 13.987,7.747 ccw(c13.987,8.255) 14.495,8.255 14.495,8.382 ccw(c13.881,8.382) 14.315,8.816 13.987,9.144 13.441,9.689 cw(c13.658,9.906) 13.352,9.906
O2A1 on Top "TOP_O2A1" (solid, pour order 33): 9.398,10.287 cw(c8.707,9.596) 9.684,9.596 9.684,8.462 9.017,7.795 cw(c8.969,7.795) 8.969,7.747 8.382,7.747 cw(c8.382,8.255) 7.874,8.255 7.874,8.382 cw(c8.487,8.382) 8.054,8.816 8.382,9.144 8.927,9.689 ccw(c8.71,9.906) 9.017,9.906
GND on Top "TOP_GND" (solid, pour order 44): -1.27,-2.81 ccw(c-0.27,-2.81) -0.27,-3.81 23.13,-3.81 ccw(c23.13,-2.81) 24.13,-2.81 24.13,30.75 ccw(c23.13,30.75) 23.13,31.75 -0.27,31.75 ccw(c-0.27,30.75) -1.27,30.75
VM on Top "VM_L01_P031" (solid, pour order 31): 20.041,0.814 20.041,2.491 ccw(c19.406,2.491) 19.406,3.126 17.501,3.126 ccw(c17.501,2.491) 16.866,2.491 16.866,0.773 ccw(c17.437,0.773) 17.501,0.205 19.431,0.205 ccw(c19.472,0.774)
VM on Top "VM_L01_P032" (solid, pour order 32): 16.078,26.44 16.078,24.764 ccw(c16.713,24.764) 16.713,24.129 18.618,24.129 ccw(c18.618,24.764) 19.253,24.764 19.253,26.481 ccw(c18.681,26.481) 18.618,27.05 16.688,27.05 ccw(c16.647,26.481)

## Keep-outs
Keep-Out Layer:
  the board outline again, w0.102

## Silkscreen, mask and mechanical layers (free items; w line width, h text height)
Top Overlay:
  text "VCCIO" at 2.032,29.972 h1.02
  text "GND" at 18.254,29.972 h1.02
  text "GND" at 2.032,27.432 h1.02
  text "ENC1A" at 2.032,24.892 h1.02
  text "ENC1B" at 2.032,22.352 h1.02
  text "MOTOR1" at 20.987,21.533 h1.27 r90
  text "GND" at 18.777,20.574 h1.02 r315
  text "ENC1N" at 2.032,19.812 h1.02
  text "CSN" at 2.032,17.272 h1.02
  text "SCK" at 2.032,14.732 h1.02
  text "VS" at 21.241,12.592 h1.02 r90
  text "SDI" at 2.032,11.608 h1.02
  text "SDO" at 2.032,9.652 h1.02
  text "GND" at 15.646,8.255 h1.02
  text "CLK16" at 2.032,7.112 h1.02
  text "ENN" at 2.032,4.572 h1.02
  text "ENC2A" at 2.032,2.032 h1.02
  text "MOTOR2" at 21.086,0.213 h1.27 r90
  text "ENC2B" at 2.032,-0.508 h1.02
  text ".BoardName" at 7.436,-1.599 h0.89
  text ".BoardVersion" at 14.842,-3.023 h0.89
  text "ENC2N" at 2.032,-3.048 h1.02
  text "GND" at 21.086,-3.262 h1.02 r90
Bottom Overlay:
  text "IC name: '.Chip'" at 13.97,30.961 h1.52 r90
  text "Supply range: VS = '.VS'" at 15.748,30.961 h1.52 r90
  text "Max. current: IRMS = '.IRMS'" at 17.526,30.961 h1.52 r90
  text "VCCIO" at 6.603,29.972 h1.02
  text "GND" at 20.911,29.972 h1.02
  text "GND" at 4.74,27.432 h1.02
  text "A1" at 20.911,27.432 h1.02
  text "ENC1A/INT" at 10.668,24.892 h1.02
  text "A2" at 20.911,24.892 h1.02
  text "ENC1B/PP" at 9.822,22.352 h1.02
  text "B1" at 20.911,22.352 h1.02
  text "ENC1N" at 6.775,19.812 h1.02
  text "B2" at 20.911,19.812 h1.02
  text "CSN" at 4.913,17.272 h1.02
  text "GND" at 20.911,17.272 h1.02
  text "SCK" at 4.913,14.732 h1.02
  text "VS" at 20.907,14.732 h1.02
  text "VS" at 20.907,12.192 h1.02
  text "SDI" at 4.574,11.608 h1.02
  text "SDO" at 4.913,9.652 h1.02
  text "GND" at 20.911,9.652 h1.02
  text "CLK16" at 6.775,7.112 h1.02
  text "B2" at 20.911,7.112 h1.02
  text "ENN" at 4.74,4.572 h1.02
  text "B1" at 20.911,4.572 h1.02
  text ".BoardName" at 17.964,2.618 h0.89
  text "ENC2A" at 6.944,2.032 h1.02
  text "A2" at 20.911,2.032 h1.02
  text ".BoardVersion" at 10.262,1.194 h0.89
  text "ENC2B" at 6.944,-0.508 h1.02
  text "A1" at 20.911,-0.508 h1.02
  text "ENC2N" at 6.944,-3.048 h1.02
  text "GND" at 20.911,-3.048 h1.02
TopAsm:
  text "'.BoardName'_V'.BoardVersion'" at 3.2,4.394 h1.27 r90

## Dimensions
23.13,31.75 to 23.13,-3.81 on Dimension
-1.27,-2.81 to 24.13,30.75 on Dimension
